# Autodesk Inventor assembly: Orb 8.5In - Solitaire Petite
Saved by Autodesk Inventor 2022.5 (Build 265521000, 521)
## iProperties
Created: 2025-02
Part Number: Orb 8.5In - Solitaire Petite
Document SubType Name: Assembly
Designer: AdminForWorker
Title: Orb 8.5In - Solitaire Petite v7
Author: AdminForWorker
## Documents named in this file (2)
- c:\worker\convert-fusion-r06-cosv3\tmp\job-1\19\temp\files\7f12bef2-acc9-47ae-8604-bbc7f61ecf5f\Orb 8.5In - Solitaire Petite v7.iam
- c:\worker\convert-fusion-r06-cosv3\tmp\job-1\19\temp\files\7f12bef2-acc9-47ae-8604-bbc7f61ecf5f\Solitaire Petite (Orb-8.5).ipt
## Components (1 placed, 1 different names)
1. Solitaire Petite (Orb-8.5):1
